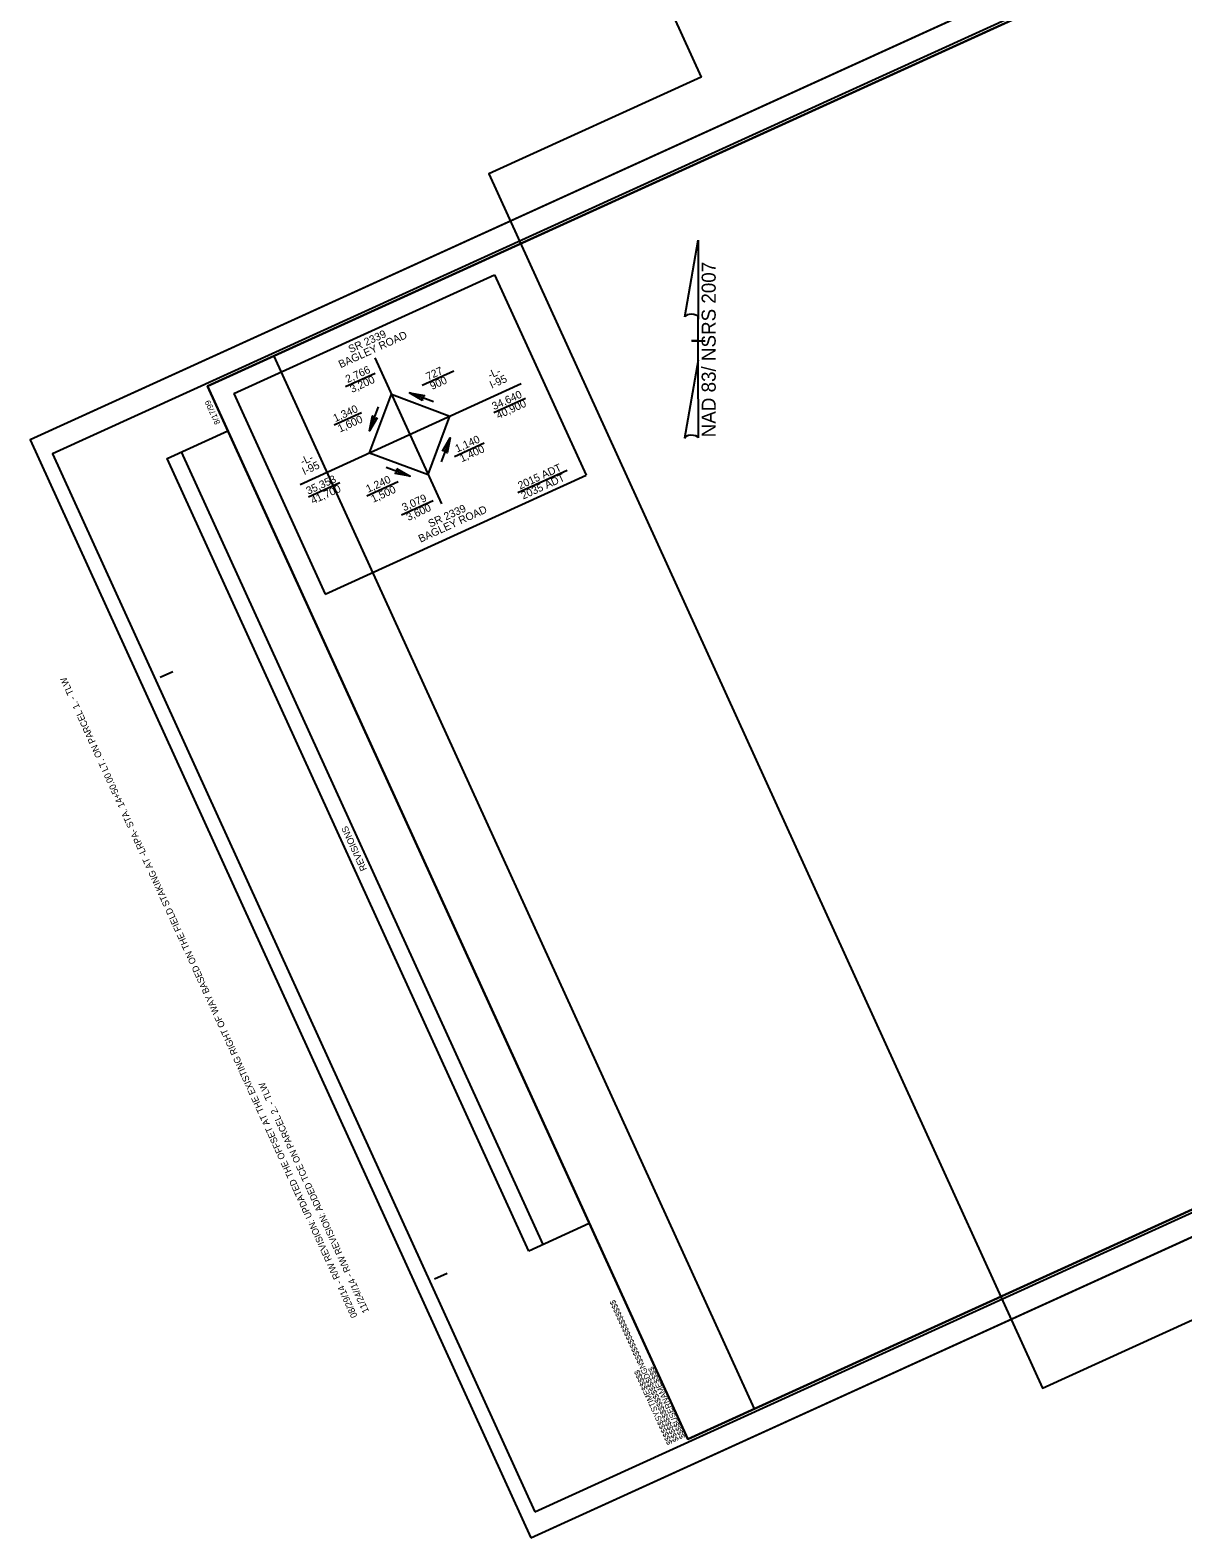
# Model space of a CAD drawing. Extents: x 2246788 to 2250969, y 662010 to 664598.
# Drawn here: x 2246788 to 2247833, y 662010 to 663378 of the extents above; entities that cross this region are included whole.
import ezdxf

# ---------------------------------------------------------------- set-up
doc = ezdxf.new("R2010")
doc.units = 0
for name, color, linetype in [('Prop Dimension Text', 7, 'Continuous'), ('Prop North Arrow NAD83 for Plan Sheets CELL', 7, 'Continuous'), ('Prop Terminator CELL', 7, 'Continuous'), ('Sheet Block Revision CELL', 7, 'Continuous'), ('Sheet Clip Boundary CELL', 7, 'Continuous'), ('Sheet Cutting Line CELL', 7, 'Continuous'), ('Sheet Layout Plan Border', 7, 'Continuous'), ('Sheet Plan CELL', 7, 'Continuous'), ('Sheet Plan Layout CELL', 7, 'Continuous'), ('Sheet Plot Border Inside CELL', 7, 'Continuous'), ('Sheet Plot Border Outside CELL', 7, 'Continuous')]:
    doc.layers.add(name, color=color, linetype=linetype)

msp = doc.modelspace()

# ---------------------------------------------------------------- linework, layer by layer
at = {"layer": 'Prop Dimension Text'}
for p, q in [((2246972.4, 663048.6), (2247209, 663156.4)), ((2247209, 663156.4), (2247291.9, 662974.4)), ((2247100.5, 663080.9), (2247160.9, 662948.4)), ((2247143.3, 663056.3), (2247171.9, 663069.3)), ((2247032.7, 662966.2), (2247233.2, 663057.6)), ((2247073.9, 663054.9), (2247100.8, 663067.1)), ((2246972.4, 663048.6), (2247055.3, 662866.6)), ((2247095.7, 662994.9), (2247115.5, 663047.9)), ((2247115.5, 663047.9), (2247168.5, 663028.1)), ((2247153.6, 663041.1), (2247131.9, 663049.2)), ((2247208.3, 663031.4), (2247236.9, 663044.4)), ((2247088.3, 663031.2), (2247063.4, 663019.9)), ((2247095.7, 663014.7), (2247103.8, 663036.4)), ((2247148.7, 662975.1), (2247168.5, 663028.1)), ((2247168.6, 663008.3), (2247160.5, 662986.5)), ((2247172.5, 662991.6), (2247199.4, 663003.9)), ((2247095.7, 662994.9), (2247148.7, 662975.1)), ((2247095.7, 662994.9), (2247148.7, 662975.1)), ((2247055.3, 662866.6), (2247291.9, 662974.4)), ((2247110.6, 662981.8), (2247132.4, 662973.7)), ((2247230.1, 662958.9), (2247274.7, 662979.2)), ((2247040.2, 662954.8), (2247068.8, 662967.8)), ((2247121.6, 662968.6), (2247093, 662955.6)), ((2247124.7, 662938.6), (2247153.3, 662951.6))]:
    msp.add_line(p, q, dxfattribs=at)
at = {"layer": 'Prop North Arrow NAD83 for Plan Sheets CELL'}
for p, q in [((2247381.4, 663118.3), (2247393.7, 663187.8)), ((2247393.7, 663187.8), (2247393.7, 663187.8)), ((2247393.7, 663187.8), (2247393.7, 663187.8)), ((2247393.7, 663187.8), (2247393.7, 663116.1)), ((2247393.7, 663078.9), (2247393.7, 663118.2)), ((2247393.7, 663116.1), (2247393.7, 663118.2)), ((2247393.1, 663096.3), (2247387.7, 663096.3)), ((2247387.7, 663096.3), (2247387.7, 663096.3)), ((2247387.8, 663096.3), (2247399.8, 663096.3)), ((2247393.7, 663078.9), (2247381.2, 663008.1)), ((2247393.8, 663008.4), (2247393.7, 663078.9))]:
    msp.add_line(p, q, dxfattribs=at)
for centre, start_param, end_param in [((2247387.6, 663117.6), 0.216388, 2.908219), ((2247387.6, 663007.8), 0.201328, 3.141593)]:
    msp.add_ellipse(centre, major_axis=(6.35, -0.05), ratio=0.461098, start_param=start_param, end_param=end_param, dxfattribs=at)
at = {"layer": 'Prop Terminator CELL'}
for points in [[(2247143.7, 663042.3), (2247131.9, 663049.2), (2247145.5, 663046.7), (2247143, 663045.1)], [(2247102.6, 663026.5), (2247095.7, 663014.7), (2247098.2, 663028.3), (2247099.8, 663025.8)], [(2247161.7, 662996.4), (2247168.6, 663008.3), (2247166.1, 662994.7), (2247164.4, 662997.2)], [(2247120.5, 662980.6), (2247132.4, 662973.7), (2247118.8, 662976.2), (2247121.3, 662977.9)]]:
    msp.add_lwpolyline(points, close=True, dxfattribs=at)
at = {"layer": 'Sheet Block Revision CELL'}
msp.add_line((2247253.1, 662276.4), (2246925.2, 662995.8), dxfattribs=at)
msp.add_lwpolyline([(2247239.9, 662270.3), (2246912, 662989.8), (2246967.1, 663014.9), (2247294.9, 662295.5)], close=True, dxfattribs=at)
at = {"layer": 'Sheet Clip Boundary CELL'}
msp.add_lwpolyline([(2248573, 662641.6), (2248489.8, 662824.8), (2248241.7, 663371.1), (2248193.9, 663457.8), (2248131.6, 663594.3), (2247008.7, 663082.6), (2247444.4, 662127.3)], close=True, dxfattribs=at)
at = {"layer": 'Sheet Cutting Line CELL'}
for p, q in [((2248319.8, 663704.8), (2246787.9, 663006.7)), ((2246787.9, 663006.7), (2247241.9, 662010.3)), ((2247241.9, 662010.3), (2248773.9, 662708.4))]:
    msp.add_line(p, q, dxfattribs=at)
at = {"layer": 'Sheet Layout Plan Border'}
msp.add_lwpolyline([(2248661.4, 662581.6), (2248242.8, 663500.1), (2248080.9, 663855.5), (2247317.9, 663507.9), (2247396.3, 663335.6), (2247203.9, 663247.9), (2247705.9, 662146.2)], close=True, dxfattribs=at)
at = {"layer": 'Sheet Plan CELL'}
for p, q in [((2246948.7, 663055.3), (2246948.7, 663055.3)), ((2246905.8, 662791.2), (2246917.2, 662796.4)), ((2247154.6, 662245.2), (2247166, 662250.4)), ((2247384.1, 662099.8), (2247384.1, 662099.8))]:
    msp.add_line(p, q, dxfattribs=at)
for points in [[(2248313.7, 663677.3), (2246948.7, 663055.3), (2247384.1, 662099.8), (2248749.1, 662721.8)], [(2247384.1, 662099.8), (2246948.7, 663055.2), (2248131.6, 663594.3), (2248193.9, 663457.8), (2248375.9, 663540.7), (2248749.1, 662721.8)]]:
    msp.add_lwpolyline(points, close=True, dxfattribs=at)
at = {"layer": 'Sheet Plan Layout CELL'}
msp.add_lwpolyline([(2246948.7, 663055.2), (2247384.1, 662099.8), (2248749, 662721.8), (2248401.3, 663484.8), (2248183.6, 663385.6), (2248095.9, 663578.1)], close=True, dxfattribs=at)
at = {"layer": 'Sheet Plot Border Inside CELL'}
msp.add_lwpolyline([(2247245.5, 662033.9), (2248761.5, 662724.7), (2248324, 663684.7), (2246808, 662993.9)], close=True, dxfattribs=at)
at = {"layer": 'Sheet Plot Border Outside CELL'}
msp.add_lwpolyline([(2247241.9, 662010.3), (2248773.9, 662708.4), (2248319.8, 663704.8), (2246787.9, 663006.7)], close=True, dxfattribs=at)

# ---------------------------------------------------------------- texts
at = {"layer": 'Prop Dimension Text'}
for s, height, rotation, p in [('BAGLEY ROAD', 7, 24.4979, (2247069.4, 663071.5)), ('SR 2339', 7, 24.4979, (2247078.3, 663085.2)), ('2,766', 7, 24.4979, (2247075.7, 663058.1)), ('727', 7, 24.4979, (2247148.6, 663060.4)), ('-L-', 7, 24.4979, (2247204.8, 663061.8)), ('3,200', 7, 24.4979, (2247079.8, 663049.1)), ('900', 7, 24.4979, (2247152.4, 663051.8)), ('I-95', 7, 24.4979, (2247206.4, 663052.9)), ('34,640', 7, 24.4979, (2247208.5, 663033.5)), ('40,900', 7, 24.4979, (2247212.4, 663025.3)), ('1,340', 7, 24.4979, (2247064.5, 663022.6)), ('1,600', 7, 24.4979, (2247068.8, 663013.2)), ('1,140', 7, 24.4979, (2247175.1, 662995)), ('1,400', 7, 24.4979, (2247179.3, 662986.2)), ('-L-', 7, 24.4979, (2247034.8, 662983.4)), ('I-95', 7, 24.4979, (2247036.4, 662974.5)), ('35,353', 7, 24.4979, (2247040, 662956.7)), ('1,240', 7, 24.4979, (2247094.3, 662958.5)), ('2015 ADT', 7, 24.4979, (2247232.1, 662961.5)), ('2035 ADT', 7, 24.4979, (2247235, 662952.4)), ('41,700', 7, 24.4979, (2247044.3, 662948)), ('1,500', 7, 24.4979, (2247098.9, 662949.4)), ('3,079', 7, 24.4979, (2247126.9, 662941.7)), ('3,600', 7, 24.4979, (2247130.8, 662932.9)), ('BAGLEY ROAD', 7, 24.4979, (2247141.8, 662913.2)), ('SR 2339', 7, 24.4979, (2247150.7, 662926.9)), ('08/29/14 - R/W REVISION: UPDATED THE OFFSET AT THE EXISTING RIGHT OF WAY BASED ON THE FIELD STAKING AT -LRPA- STA. 14+50.00 LT. ON PARCEL 1. - TLW', 6, 114.4979, (2247084.8, 662211.5)), ('11/24//14 - R/W REVISION: ADDED TCE ON PARCEL 2. - TLW', 6, 114.4979, (2247095.3, 662215.8))]:
    msp.add_text(s, height=height, rotation=rotation, dxfattribs=at).set_placement(p)
at = {"layer": 'Prop North Arrow NAD83 for Plan Sheets CELL'}
msp.add_text('NAD 83/ NSRS 2007', height=12.75, rotation=90, dxfattribs=at).set_placement((2247409.5, 663008.9))
at = {"layer": 'Sheet Block Revision CELL'}
msp.add_text('REVISIONS', height=6, rotation=114.4979, dxfattribs=at).set_placement((2247093.4, 662617))
at = {"layer": 'Sheet Plan CELL'}
for s, p in [('8/17/99', (2246960.4, 663021.9)), ('$$$$$$$$$$$$$$$$DGN$$$$$$$$$$$$$$$$', (2247376.2, 662098.8)), ('$$$$USERNAME$$$$', (2247382.1, 662101.5)), ('$$$$$$SYSTIME$$$$$', (2247370.6, 662096.2))]:
    msp.add_text(s, height=5.25, rotation=114.4979, dxfattribs=at).set_placement(p)

doc.saveas('drawing.dxf')
